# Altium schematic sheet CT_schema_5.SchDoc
size 248 x 201 mm
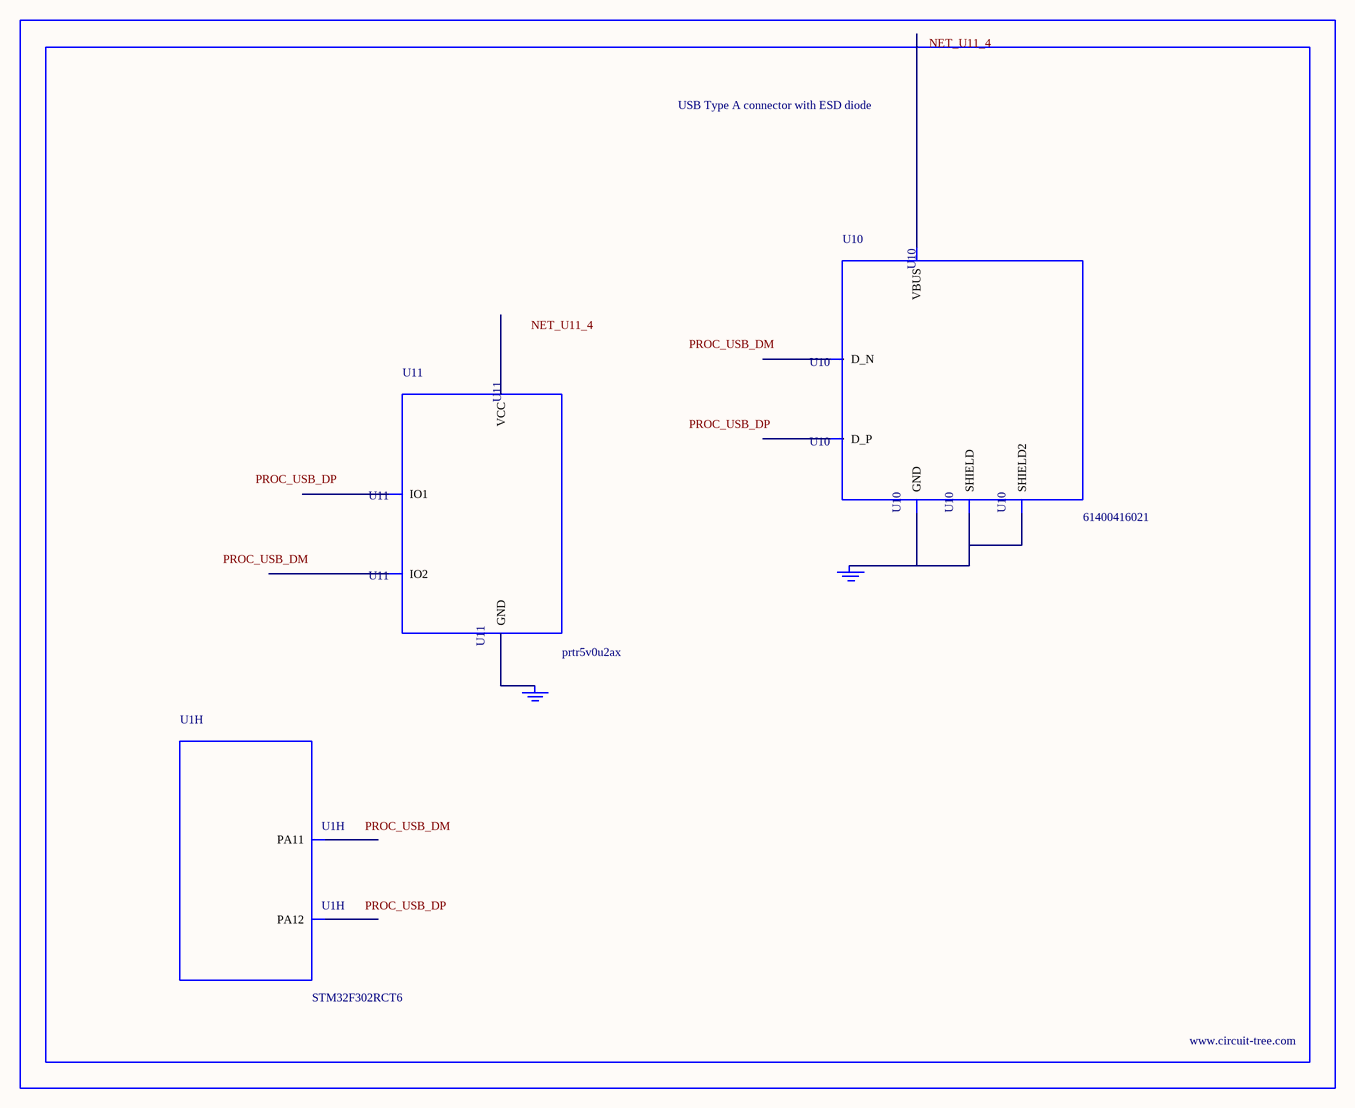
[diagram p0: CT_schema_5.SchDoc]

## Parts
BORDER4  (no value)
GND_INSTANCE_4_0  (no value)
GND_INSTANCE_4_1  (no value)
U1  STM32F302RCT6  [LQFP64]  (part H of 8)
U10  61400416021  [USB-A-H]
U11  prtr5v0u2ax  [SOT143B]

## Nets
NetGND_INSTANCE_4_0_0: GND_INSTANCE_4_0.0(GND) U10.4(GND) U10.5(SHIELD) U10.6(SHIELD2)
NetGND_INSTANCE_4_1_0: GND_INSTANCE_4_1.0(GND) U11.1(GND)

Not connected (* = marked no-connect by the designer): U1 44(PA11) 45(PA12); U10 1(VBUS) 2(D_N) 3(D_P); U11 2(IO1) 3(IO2) 4(VCC)

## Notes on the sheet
- Labels drawn without touching a wire or pin: NET_U11_4, PROC_USB_DM, PROC_USB_DP

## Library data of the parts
BORDER4 = BORDER_PAGE4
GND_INSTANCE_4_0 GND_INSTANCE_4_1 = GND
